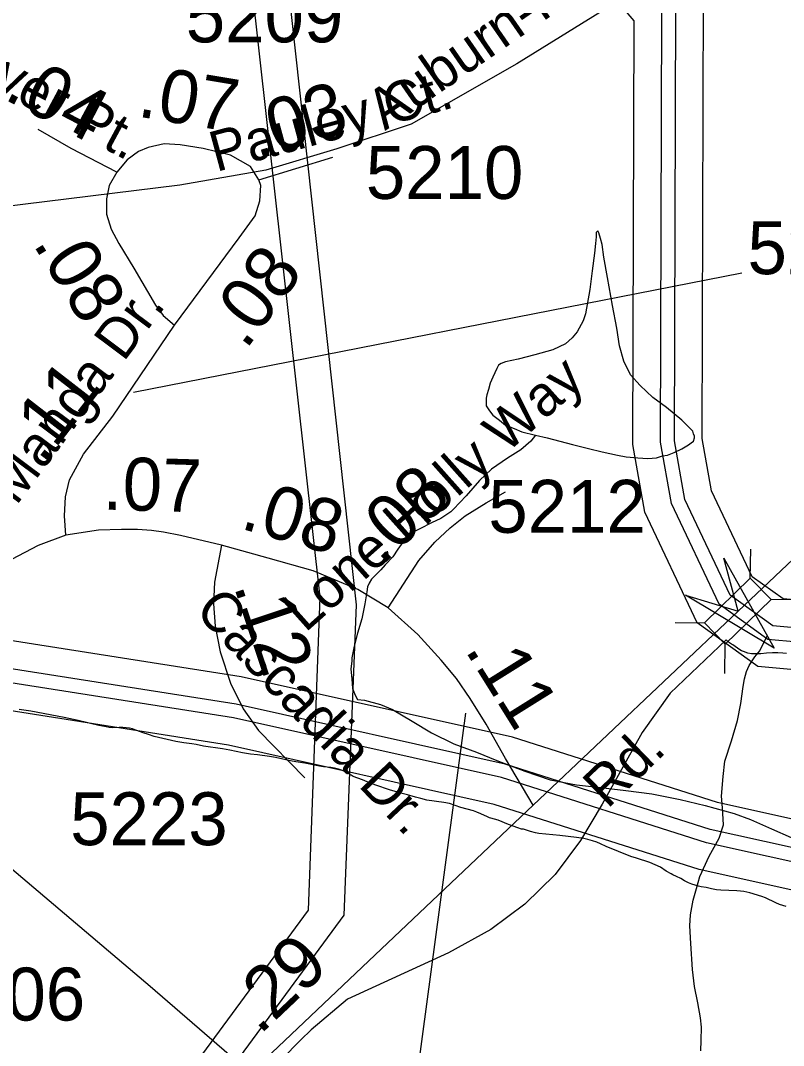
# Model space of a CAD drawing. Extents: x 2169602 to 2449496, y 721995 to 810662.
# Drawn here: x 2385883 to 2387685, y 783404 to 785825 of the extents above; entities that cross this region are included whole.
import ezdxf

# ---------------------------------------------------------------- set-up
doc = ezdxf.new("R2010")
doc.units = 0
doc.layers.add('Default', color=7, linetype='Continuous')

msp = doc.modelspace()

# ---------------------------------------------------------------- linework, layer by layer
at = {"layer": 'Default'}
for p, q in [((2386149.7, 784946.9), (2387586.1, 785228.9)), ((2387606.3, 784507.6), (2387607.3, 784576.6)), ((2387654.4, 784458.1), (2387723.4, 784457.2)), ((2387428.8, 784403.4), (2387497.8, 784402.4)), ((2387546.1, 784282.9), (2387547, 784351.9)), ((2386934, 784189.1), (2386669.6, 782215.1))]:
    msp.add_line(p, q, dxfattribs=at)
for points in [[(2385516.1, 794624.8), (2385508.5, 794499.5), (2385507.3, 794440.1), (2385504.9, 794341.8), (2385507.3, 794252), (2385509.7, 794129.4), (2386589.6, 784463), (2386562.5, 783723.6), (2379965, 774755.3), (2379098.1, 772209.8)], [(2385609.5, 794604.6), (2385600.6, 794401), (2385600.6, 794279.8), (2385602, 794189.7), (2386675.9, 784444.9), (2386646.9, 783712.3), (2380042.2, 774729.7), (2379098.1, 771950.4)], [(2393230.6, 788326.1), (2392891.6, 787980.5), (2392407.1, 787494.7), (2392252.3, 787329.2), (2392139.3, 787188.9), (2391757.3, 786638.1), (2391627.6, 786491.5), (2391472.7, 786363.8), (2391330.4, 786263.2), (2391088.7, 786146), (2390655.5, 785953.3), (2390481.8, 785869.5), (2390326.9, 785769), (2390070.6, 785609.8), (2389821.5, 785467.4), (2389645.7, 785408.8), (2389478.3, 785358.5), (2389275.3, 785322.9), (2388692.5, 785251.7), (2388493.7, 785209.8), (2388397.4, 785161.7), (2388278.1, 785082.1), (2387722.5, 784566.9), (2387577.7, 784429.9)], [(2387331.8, 785823.8), (2387180.6, 786002.2), (2386997.4, 786075.3), (2386337.4, 786226.5)], [(2388064.3, 783883.6), (2387957, 783883.1), (2387528.5, 783978), (2387044.6, 784132.3), (2386404.5, 784274.5), (2385688, 784387.5), (2385068.4, 784535.3), (2384667.8, 784571.8), (2384595.2, 784624), (2384498.9, 784826.9), (2384477.1, 784950.3), (2384480.2, 785996.6)], [(2388078.5, 783818), (2387949.9, 783817.5), (2387511.4, 783914.6), (2387027.5, 784068.8), (2386392.2, 784210), (2385675.3, 784323.1), (2385057.8, 784470.3), (2384644, 784508), (2384543.2, 784580.6), (2384435.8, 784806.7), (2384411.4, 784944.6), (2384414.5, 785972.6)], [(2388085.6, 783785.3), (2387946.4, 783784.7), (2387502.8, 783882.9), (2387018.9, 784037.1), (2386386.1, 784177.7), (2385668.9, 784290.9), (2385052.4, 784437.9), (2384632.1, 784476.2), (2384517.2, 784558.9), (2384404.3, 784796.6), (2384378.6, 784941.8), (2384381.7, 785960.6)], [(2388077.2, 783719.6), (2387939.4, 783719), (2387485.7, 783819.5), (2387001.8, 783973.7), (2386373.9, 784113.2), (2385656.2, 784226.5), (2385041.8, 784373), (2384608.3, 784412.5), (2384465.1, 784515.5), (2384341.2, 784776.5), (2384313, 784936.1), (2384316, 785936.7)], [(2387311.1, 785881.8), (2387054.7, 785722.7), (2386805.7, 785580.3), (2386629.9, 785521.6), (2386462.5, 785471.4), (2386259.5, 785435.8), (2385676.6, 785364.5), (2385477.8, 785322.7), (2385381.6, 785274.5), (2385262.3, 785194.9), (2384706.6, 784679.7), (2384561.9, 784542.7)], [(2391080.1, 783770.8), (2390972.8, 783770.3), (2390544.3, 783865.2), (2390060.4, 784019.4), (2389420.3, 784161.6), (2388703.9, 784274.7), (2388084.2, 784422.4), (2387683.6, 784458.9), (2387611, 784511.2), (2387514.7, 784714), (2387492.9, 784837.5), (2387496.1, 785883.8)], [(2391101.5, 783672.4), (2390962.2, 783671.8), (2390518.7, 783770.1), (2390034.7, 783924.3), (2389401.9, 784064.9), (2388684.7, 784178.1), (2388068.3, 784325.1), (2387647.9, 784363.3), (2387533, 784446.1), (2387420.1, 784683.8), (2387394.5, 784829), (2387397.5, 785847.8)], [(2391094.3, 783705.2), (2390965.8, 783704.7), (2390527.2, 783801.8), (2390043.3, 783956), (2389408.1, 784097.2), (2388691.1, 784210.3), (2388073.6, 784357.5), (2387659.8, 784395.2), (2387559, 784467.8), (2387451.6, 784693.9), (2387427.3, 784831.8), (2387430.4, 785859.8)], [(2391093, 783606.8), (2390955.2, 783606.2), (2390501.6, 783706.6), (2390017.6, 783860.9), (2389389.7, 784000.4), (2388672, 784113.6), (2388057.6, 784260.1), (2387624.1, 784299.6), (2387480.9, 784402.7), (2387357, 784663.7), (2387328.8, 784823.3), (2387331.8, 785823.8)], [(2386110.4, 785466.3), (2386002.9, 785522.3), (2385924.6, 785567.1)], [(2386446.2, 785448.4), (2386426.1, 785479.7), (2386379.1, 785506.6), (2386314.1, 785522.3), (2386260.4, 785531.3), (2386222.3, 785533.5), (2386184.3, 785524.5), (2386161.9, 785515.6), (2386135, 785495.4), (2386110.4, 785466.3)], [(2386446.2, 785448.4), (2386620.9, 785502.1)], [(2386110.4, 785466.3), (2386092.5, 785434.9), (2386085.8, 785403.6), (2386085.8, 785367.7), (2386097, 785331.9), (2386114.9, 785298.3), (2386150.7, 785240), (2386202.2, 785152.7), (2386220.1, 785128), (2386247, 785105.6)], [(2386247, 785105.6), (2386399.2, 785311.7), (2386437.3, 785363.2), (2386448.5, 785399.1), (2386450.7, 785434.9), (2386446.2, 785448.4)], [(2387098.9, 784845.4), (2387126.7, 784839.6), (2387186.6, 784823.6), (2387224.5, 784813.8), (2387256.7, 784806.1), (2387292.8, 784798.2), (2387312.9, 784794.4), (2387340.6, 784792.2), (2387364.6, 784790.6), (2387384.9, 784792.4), (2387398.8, 784796.8), (2387410.5, 784798.7), (2387426.5, 784804.8), (2387444.6, 784813), (2387460.6, 784822.8), (2387466.3, 784827.1), (2387472.5, 784831.1), (2387474.7, 784838.9), (2387474.5, 784843), (2387472, 784848.9), (2387470.6, 784854.9), (2387462.6, 784863), (2387444.4, 784880.8), (2387408.1, 784910.6), (2387375.9, 784934.5), (2387346.1, 784962.5), (2387323.6, 784988.2), (2387307.8, 785020.3), (2387297.5, 785056.3), (2387291.4, 785098.2), (2387281.1, 785152.1), (2387268.8, 785218), (2387260.6, 785265.9), (2387256.7, 785295.7), (2387252.6, 785309.7), (2387248.5, 785323.7), (2387246.3, 785327.7), (2387242.6, 785323.8), (2387242.6, 785313.6), (2387240.5, 785297.8), (2387238.5, 785275.7), (2387232.8, 785233.6), (2387227.2, 785189.8), (2387217.4, 785131.7), (2387211.4, 785115.6), (2387197.7, 785089.6), (2387185.6, 785075.6), (2387169.6, 785061.4), (2387139.7, 785047.3), (2387097.8, 785035.4), (2387057.8, 785025.2), (2387027.9, 785018.8), (2387017.9, 785015), (2387012.1, 785011), (2387007.8, 785002.8), (2386998, 784982.7), (2386991.8, 784968.6), (2386987.9, 784953), (2386984.2, 784940.6), (2386982.4, 784932.8), (2386982.4, 784924.7), (2386982.4, 784914.9), (2386990.2, 784902.8), (2386998.4, 784892.7), (2387014.2, 784880.9), (2387028.3, 784869), (2387048.8, 784861.1), (2387066.5, 784853.2), (2387098.9, 784845.4)], [(2385990.3, 784609.7), (2385987.2, 784655.3), (2385989.5, 784700.1), (2385998.4, 784740.4), (2386032, 784800.9), (2386101.4, 784890.5), (2386247, 785105.6)], [(2387098.9, 784845.4), (2387088.4, 784831.2), (2387064.6, 784811.2), (2387032.8, 784790.9), (2386994.9, 784765), (2386967.2, 784738.8), (2386935.2, 784702.6), (2386905.3, 784670.7), (2386899.5, 784664.6), (2386875.6, 784648.4), (2386853.6, 784638.3), (2386825.7, 784624.3), (2386805.6, 784613.9), (2386798, 784606.2), (2386789.8, 784598.1), (2386773.8, 784576.1), (2386762, 784558.1), (2386744.1, 784539.7), (2386734.1, 784527.8), (2386722.2, 784515.8)], [(2386751.6, 784437.7), (2386823.5, 784549.4), (2386861.4, 784593), (2386897.3, 784627), (2386933.3, 784655.4), (2386982.5, 784685.7), (2387028.6, 784711.4)], [(2386358, 784585.4), (2386261.2, 784608.7), (2386221, 784616.7), (2386192.6, 784620.4), (2386159.4, 784622.6), (2386121.9, 784622.6), (2386067.2, 784621.5), (2385990.3, 784609.7)], [(2385990.3, 784609.7), (2385924.8, 784585), (2385861.8, 784552.1), (2385806.9, 784516.4), (2385757.6, 784480.8), (2385697.3, 784428.6), (2385642.5, 784365.5)], [(2386358, 784585.4), (2386341, 784498.3), (2386339.1, 784447.2), (2386342.9, 784394.2), (2386354.3, 784333.6), (2386378.9, 784259.7), (2386409.1, 784199.2), (2386445.1, 784148), (2386554.8, 784036.3)], [(2386751.6, 784437.7), (2386679.7, 784481.3), (2386573.8, 784524.8), (2386467.8, 784555.1), (2386358, 784585.4)], [(2386722.2, 784515.8), (2386711.9, 784505.6), (2386706.6, 784495.8), (2386702.3, 784487.6), (2386700.6, 784475.7), (2386696.3, 784447.5), (2386688.7, 784411.8), (2386678.7, 784377.6), (2386670.7, 784347.5), (2386665.4, 784319.6), (2386665.2, 784311.5), (2386663.1, 784293.6), (2386665.4, 784269.7), (2386667.2, 784247.5), (2386673.2, 784231.6), (2386679.1, 784221.7)], [(2387093.8, 783971.8), (2387027.9, 784081.8), (2386982.5, 784163.2), (2386944.6, 784223.8), (2386912.5, 784271.1), (2386876.5, 784314.6), (2386821.6, 784375.2), (2386751.6, 784437.7)], [(2387577.7, 784429.9), (2387093.8, 783971.8)], [(2387489.2, 783391.6), (2387490.6, 783415.7), (2387490.8, 783447.4), (2387488.6, 783469.6), (2387482.6, 783505.4), (2387474.6, 783543.5), (2387470.1, 783583.5), (2387466, 783645.4), (2387463.6, 783687.1), (2387465.4, 783713.2), (2387471.6, 783747.2), (2387479.1, 783775.2), (2387487.1, 783803.2), (2387509.3, 783851.4), (2387532.9, 783893.7), (2387542.9, 783925.4), (2387540.7, 783965.5), (2387538.4, 783993.4), (2387542.3, 784039.5), (2387546.2, 784075.4), (2387561.8, 784123.7), (2387575.7, 784171.5), (2387583.7, 784211.7), (2387589.1, 784251.8), (2387592.9, 784269.9), (2387597.3, 784287.5), (2387603.4, 784301.6), (2387616.9, 784321.9), (2387629, 784335.9), (2387646.5, 784371.7)], [(2387600.5, 784331), (2387590, 784334.5), (2387585.5, 784336.5), (2387581.2, 784338.8), (2387570.2, 784346.8), (2387565, 784350.3), (2387561.7, 784352.2), (2387557.5, 784355.3), (2387549.5, 784362.4), (2387416.7, 784236.2), (2387351.2, 784143.6), (2387256.2, 783974.2), (2387205.2, 783888.1), (2387145.5, 783808.3), (2387073.7, 783738.1), (2386993.7, 783678), (2386893.7, 783623.2), (2386655.5, 783514), (2386569.2, 783440.9), (2386544.7, 783417.3), (2386532.5, 783405.2), (2386490.7, 783361.7)], [(2387600.5, 784331), (2387590, 784334.5), (2387585.5, 784336.5), (2387581.2, 784338.8), (2387570.2, 784346.8), (2387565, 784350.3), (2387561.7, 784352.2), (2387557.5, 784355.3), (2387549.5, 784362.4), (2387416.7, 784236.2), (2387351.2, 784143.6), (2387256.2, 783974.2), (2387205.2, 783888.1), (2387145.5, 783808.3), (2387073.7, 783738.1), (2386993.7, 783678), (2386893.7, 783623.2), (2386655.5, 783514), (2386569.2, 783440.9), (2386544.7, 783417.3), (2386532.5, 783405.2), (2386490.7, 783361.7)], [(2387691.5, 784329.6), (2387683, 784330.9), (2387671.2, 784331.7), (2387658.7, 784331.8), (2387644.7, 784330.5), (2387631.5, 784329.2), (2387622.7, 784329.3), (2387612.2, 784329.5), (2387609.2, 784329.4), (2387600.5, 784331)], [(2387691.5, 784329.6), (2387683, 784330.9), (2387671.2, 784331.7), (2387658.7, 784331.8), (2387644.7, 784330.5), (2387631.5, 784329.2), (2387622.7, 784329.3), (2387612.2, 784329.5), (2387609.2, 784329.4), (2387600.5, 784331)], [(2386679.1, 784221.7), (2386695.3, 784219.7), (2386733.2, 784209.9), (2386761.5, 784198), (2386807.9, 784170.2), (2386853.8, 784142.6), (2386906.1, 784116.9), (2386959.6, 784097), (2387007.8, 784077.1), (2387074, 784051.7), (2387134.1, 784031.7), (2387195.8, 784019.9), (2387266, 784012.1), (2387312.3, 784006.3), (2387373.8, 783998.6), (2387440.5, 783984.9), (2387500.1, 783971.4), (2387568.4, 783951.8), (2387606.4, 783937.9), (2387656.4, 783916.2), (2387748.9, 783874.6)], [(2387490.2, 783779.1), (2387484.2, 783780.4), (2387476.2, 783782.6), (2387467.9, 783785.4), (2387460.7, 783788.3), (2387451.2, 783793), (2387441.9, 783798.4), (2387432.2, 783803.4), (2387423.4, 783807.3), (2387419.2, 783809.4), (2387407.4, 783816.3), (2387394.2, 783825.3), (2387381.9, 783831.1), (2387368.9, 783836.3), (2387337.7, 783846.6), (2387324.4, 783850.9), (2387265.9, 783873.8), (2387252.4, 783880.6), (2387243.7, 783884.3), (2387233.7, 783887.8), (2387222.7, 783890.8), (2387212.9, 783892.8), (2387196.2, 783895.2), (2387156.2, 783899.9), (2387106.9, 783905), (2387098.7, 783906.4), (2387087.2, 783909.3), (2387070.4, 783914.8), (2387066.4, 783915.3), (2387057.7, 783918), (2387035.4, 783926.2), (2387010.7, 783936.2), (2386993.4, 783941.1), (2386990.2, 783942), (2386985.4, 783943.9), (2386969.7, 783951.3), (2386960.4, 783955.2), (2386952.4, 783958.1), (2386922.4, 783966.6), (2386896.4, 783975.4), (2386882.9, 783977.8), (2386842.7, 783984), (2386828.2, 783987.3), (2386815.9, 783990.6), (2386797.2, 783996.2), (2386781.2, 784000.3), (2386772.9, 784002.4), (2386754.7, 784008), (2386721.7, 784018.8), (2386706.9, 784024.6), (2386690.7, 784031.4), (2386668.7, 784039.8), (2386663.7, 784042.4), (2386651.4, 784049.8), (2386643.2, 784053.8), (2386633.9, 784057.2), (2386624.7, 784059.4), (2386615.9, 784060.5), (2386598.9, 784062), (2386588.7, 784063.7), (2386554.4, 784070.8), (2386532.9, 784074), (2386520.7, 784076.2), (2386502.2, 784080.5), (2386484.9, 784084.6), (2386470.9, 784087.1), (2386442.9, 784090.6), (2386426.2, 784092.4), (2386406.9, 784095.5), (2386377.4, 784101.4), (2386360.4, 784104.6), (2386315.2, 784111.1), (2386297.9, 784114.8), (2386287.9, 784116.6), (2386268.4, 784119.1), (2386259.4, 784120.3), (2386249.7, 784122), (2386198.7, 784134), (2386185.4, 784138.4), (2386172.7, 784143), (2386155.2, 784148.8), (2386151.7, 784150.4), (2386147.2, 784152.1), (2386140.4, 784153.4), (2386132.7, 784154.4), (2386124.4, 784155), (2386115.7, 784155.1), (2386100.4, 784154.8), (2386092.2, 784155.4), (2386085.2, 784156.4), (2386068.4, 784160), (2386019.2, 784171.6), (2385986.2, 784179), (2385907.7, 784193.6), (2385880.2, 784197.9)], [(2387490.2, 783779.1), (2387484.2, 783780.4), (2387476.2, 783782.6), (2387467.9, 783785.4), (2387460.7, 783788.3), (2387451.2, 783793), (2387441.9, 783798.4), (2387432.2, 783803.4), (2387423.4, 783807.3), (2387419.2, 783809.4), (2387407.4, 783816.3), (2387394.2, 783825.3), (2387381.9, 783831.1), (2387368.9, 783836.3), (2387337.7, 783846.6), (2387324.4, 783850.9), (2387265.9, 783873.8), (2387252.4, 783880.6), (2387243.7, 783884.3), (2387233.7, 783887.8), (2387222.7, 783890.8), (2387212.9, 783892.8), (2387196.2, 783895.2), (2387156.2, 783899.9), (2387106.9, 783905), (2387098.7, 783906.4), (2387087.2, 783909.3), (2387070.4, 783914.8), (2387066.4, 783915.3), (2387057.7, 783918), (2387035.4, 783926.2), (2387010.7, 783936.2), (2386993.4, 783941.1), (2386990.2, 783942), (2386985.4, 783943.9), (2386969.7, 783951.3), (2386960.4, 783955.2), (2386952.4, 783958.1), (2386922.4, 783966.6), (2386896.4, 783975.4), (2386882.9, 783977.8), (2386842.7, 783984), (2386828.2, 783987.3), (2386815.9, 783990.6), (2386797.2, 783996.2), (2386781.2, 784000.3), (2386772.9, 784002.4), (2386754.7, 784008), (2386721.7, 784018.8), (2386706.9, 784024.6), (2386690.7, 784031.4), (2386668.7, 784039.8), (2386663.7, 784042.4), (2386651.4, 784049.8), (2386643.2, 784053.8), (2386633.9, 784057.2), (2386624.7, 784059.4), (2386615.9, 784060.5), (2386598.9, 784062), (2386588.7, 784063.7), (2386554.4, 784070.8), (2386532.9, 784074), (2386520.7, 784076.2), (2386502.2, 784080.5), (2386484.9, 784084.6), (2386470.9, 784087.1), (2386442.9, 784090.6), (2386426.2, 784092.4), (2386406.9, 784095.5), (2386377.4, 784101.4), (2386360.4, 784104.6), (2386315.2, 784111.1), (2386297.9, 784114.8), (2386287.9, 784116.6), (2386268.4, 784119.1), (2386259.4, 784120.3), (2386249.7, 784122), (2386198.7, 784134), (2386185.4, 784138.4), (2386172.7, 784143), (2386155.2, 784148.8), (2386151.7, 784150.4), (2386147.2, 784152.1), (2386140.4, 784153.4), (2386132.7, 784154.4), (2386124.4, 784155), (2386115.7, 784155.1), (2386100.4, 784154.8), (2386092.2, 784155.4), (2386085.2, 784156.4), (2386068.4, 784160), (2386019.2, 784171.6), (2385986.2, 784179), (2385907.7, 784193.6), (2385880.2, 784197.9)], [(2387093.8, 783971.8), (2386735.7, 783632.9), (2386431.2, 783343.9), (2386362.2, 783249.6), (2386302.5, 783138.6), (2386270.6, 783037), (2386238.9, 782764.9)], [(2385774, 783895.9), (2386189, 783544.5), (2386404.6, 783357.9)], [(2387690.9, 783732.2), (2387683.4, 783734.6), (2387675.2, 783737.6), (2387666.9, 783740.9), (2387642.2, 783753.1), (2387633.7, 783756.3), (2387605.4, 783765.1), (2387591.2, 783767.9), (2387583.2, 783768.9), (2387574.4, 783769.6), (2387536.9, 783770.9), (2387526.7, 783771.9), (2387514.4, 783774.6), (2387502.4, 783777.1), (2387490.2, 783779.1)], [(2387690.9, 783732.2), (2387683.4, 783734.6), (2387675.2, 783737.6), (2387666.9, 783740.9), (2387642.2, 783753.1), (2387633.7, 783756.3), (2387605.4, 783765.1), (2387591.2, 783767.9), (2387583.2, 783768.9), (2387574.4, 783769.6), (2387536.9, 783770.9), (2387526.7, 783771.9), (2387514.4, 783774.6), (2387502.4, 783777.1), (2387490.2, 783779.1)]]:
    msp.add_lwpolyline(points, dxfattribs=at)
for points in [[(2387544, 784555.4), (2387662.5, 784342.3), (2387453.3, 784467.6), (2387577.7, 784429.9)], [(2387497.8, 784402.4), (2387606.1, 784507.8), (2387655.3, 784457.2), (2387547, 784351.9)]]:
    msp.add_lwpolyline(points, close=True, dxfattribs=at)

# ---------------------------------------------------------------- texts
for s, height, rotation, p in [('Auburn-Knightdale', 95, 34.691, (2386743.5, 785563.5)), ('Sunriver Pt.', 95, 331.7216, (2385551.2, 785807.2)), ('.04', 125, 332.4745, (2385840.6, 785640.9)), ('.07', 125, 350.5316, (2386156.7, 785598.4)), ('Pauley Ct.', 95, 15.1996, (2386344.9, 785466.7)), ('.03', 125, 17.1122, (2386441.7, 785496.5)), ('.08', 125, 301.5926, (2385910.8, 785297.6)), ('.08', 125, 53.5469, (2386415, 785045)), ('La Manga Dr.', 95, 53.2357, (2385767.2, 784535.8)), ('Lone Holly Way', 95, 41.694, (2386555.3, 784377.6)), ('.11', 125, 52.2407, (2385936, 784775)), ('.07', 125, 358.2628, (2386076.3, 784670)), ('.08', 125, 43.4684, (2386736.3, 784535.8)), ('.08', 125, 344.0453, (2386399.2, 784625.9)), ('Cascadia Dr.', 95, 313.2566, (2386291.6, 784429.4)), ('.12', 125, 288.425, (2386386, 784489.5)), ('.11', 125, 301.9904, (2386930.8, 784338.8)), ('Rd.', 95, 43.9745, (2387268.7, 783961.3)), ('.29', 125, 43.5048, (2386447.6, 783427.3))]:
    msp.add_text(s, height=height, rotation=rotation, dxfattribs=at).set_placement(p)
for s, p in [('5209', (2386273.3, 785773.1)), ('5210', (2386698.5, 785403.4)), ('5209', (2387599.7, 785225.7)), ('5212', (2386987.6, 784615)), ('5223', (2386000.4, 783877.3)), ('5206', (2385663.9, 783463.2))]:
    msp.add_text(s, height=125, dxfattribs=at).set_placement(p)

doc.saveas('drawing.dxf')
